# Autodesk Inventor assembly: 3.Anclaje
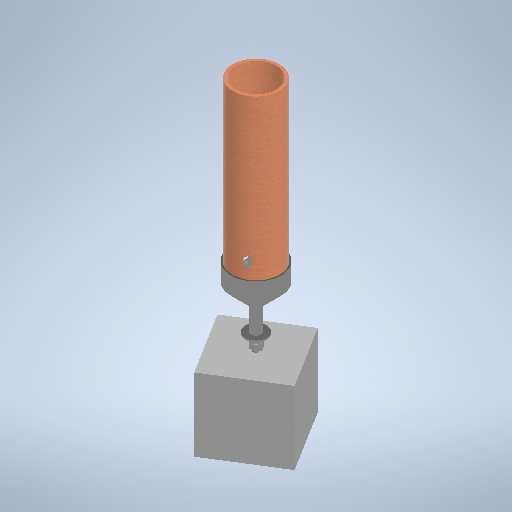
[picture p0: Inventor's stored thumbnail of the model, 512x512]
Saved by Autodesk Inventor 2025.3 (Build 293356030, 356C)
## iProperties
Created: 2025-10
Part Number: 3.Anclaje
Document SubType Name: Assembly
Designer: User
Author: User
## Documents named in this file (10)
- C:\Users\luisa\OneDrive\Documentos\Investigacion\ANCLAJES\6. Anclaje de Pernos\3.Anclaje.iam
- C:\Users\luisa\OneDrive\Documentos\Investigacion\ANCLAJES\6. Anclaje de Pernos\1.Barra horizontal 12mm.ipt
- C:\Users\luisa\OneDrive\Documentos\Investigacion\ANCLAJES\6. Anclaje de Pernos\2.Perfil de hierro.ipt
- C:\Users\luisa\OneDrive\Documentos\Investigacion\ANCLAJES\6. Anclaje de Pernos\3.Barra Vertical 20mm.ipt
- C:\Users\luisa\OneDrive\Documentos\Investigacion\ANCLAJES\6. Anclaje de Pernos\4.Bloque concreto.ipt
- C:\Users\luisa\OneDrive\Documentos\Investigacion\ANCLAJES\6. Anclaje de Pernos\0.Guadua.ipt
- C:\Users\User\OneDrive - Institucion Universitaria Colegio Mayor de Antioquia\Documentos\Inventor\Content Center Files\R2025\es-ES\ANSI B18.22 M\ANSI B18.22M - 12 N.ipt
- C:\Users\luisa\OneDrive\Documentos\Investigacion\ANCLAJES\6. Anclaje de Pernos\7.Tuerca 20mm.ipt
- C:\Users\luisa\OneDrive\Documentos\Investigacion\ANCLAJES\6. Anclaje de Pernos\8.Relleno de concreto.ipt
- C:\Users\luisa\OneDrive\Documentos\Investigacion\ANCLAJES\6. Anclaje de Pernos\5.Tuerca 12mm.ipt
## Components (12 placed, 9 different names)
1. 1.Barra horizontal 12mm:1 — Mate:2, Rigid:1, Mate:18, Mate:20
2. 2.Perfil de hierro:1 — Mate:1, Mate:3, Rigid:3, Mate:16, Rigid:4
3. 3.Barra Vertical 20mm:1 — Mate:1, Mate:2, Rigid:1, Rigid:2, Mate:10, Mate:15, Mate:24
4. 4.Bloque concreto:1 — Rigid:2, Mate:3
5. 0.Guadua:1 — Rigid:3
6. Arandela plana (Métrico) 12 N:1 — Mate:10, Mate:19
7. AS 1252 - Métrico M20:3 — Mate:15, Mate:16, Mate:22
8. 8.Relleno de concreto:1 — Rigid:4
9. AS 1252 - Métrico M12:3 — Mate:18, Mate:19
10. AS 1252 - Métrico M12:4 — Mate:20, Mate:25
11. AS 1252 - Métrico M20:4 — Mate:22
12. Arandela plana (Métrico) 12 N:2 — Mate:24, Mate:25
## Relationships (16: Mate 12, WeldJoint 4)
- Mate:1: 2.Perfil de hierro:1 ↔ 3.Barra Vertical 20mm:1
- Mate:2: 1.Barra horizontal 12mm:1 ↔ 3.Barra Vertical 20mm:1
- Rigid:1 [WeldJoint]: 1.Barra horizontal 12mm:1 ↔ 3.Barra Vertical 20mm:1
- Rigid:2 [WeldJoint]: 3.Barra Vertical 20mm:1 ↔ 4.Bloque concreto:1
- Mate:3: 2.Perfil de hierro:1 ↔ 4.Bloque concreto:1
- Rigid:3 [WeldJoint]: 2.Perfil de hierro:1 ↔ 0.Guadua:1
- Mate:10: 3.Barra Vertical 20mm:1 ↔ Arandela plana (Métrico) 12 N:1
- Mate:15: 3.Barra Vertical 20mm:1 ↔ AS 1252 - Métrico M20:3
- Mate:16: 2.Perfil de hierro:1 ↔ AS 1252 - Métrico M20:3
- Rigid:4 [WeldJoint]: 2.Perfil de hierro:1 ↔ 8.Relleno de concreto:1
- Mate:18: 1.Barra horizontal 12mm:1 ↔ AS 1252 - Métrico M12:3
- Mate:19: Arandela plana (Métrico) 12 N:1 ↔ AS 1252 - Métrico M12:3
- Mate:20: 1.Barra horizontal 12mm:1 ↔ AS 1252 - Métrico M12:4
- Mate:22: AS 1252 - Métrico M20:3 ↔ AS 1252 - Métrico M20:4
- Mate:24: 3.Barra Vertical 20mm:1 ↔ Arandela plana (Métrico) 12 N:2
- Mate:25: AS 1252 - Métrico M12:4 ↔ Arandela plana (Métrico) 12 N:2
